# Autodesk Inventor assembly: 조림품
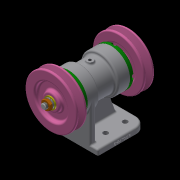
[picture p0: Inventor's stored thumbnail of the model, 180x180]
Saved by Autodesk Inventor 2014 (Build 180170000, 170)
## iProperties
Created: 2020-06
Part Number: 조림품
Document SubType Name: Assembly
Designer: kh
Author: kh
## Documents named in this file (12)
- C:\Users\kh\Desktop\700606V1034\조림품.iam
- C:\Users\kh\Desktop\700606V1034\본체.ipt
- C:\Users\kh\Desktop\700606V1034\베어링 6204.ipt
- C:\Users\kh\Desktop\700606V1034\축.ipt
- C:\Users\kh\Desktop\700606V1034\커버.ipt
- C:\Users\kh\Desktop\700606V1034\오일 실 20 32 5.ipt
- C:\Users\kh\Desktop\700606V1034\Ű 5x5x12.ipt
- C:\Users\kh\Desktop\700606V1034\V-벨트풀리.ipt
- C:\Users\kh\Desktop\700606V1034\평면 와셔 10x21.ipt
- C:\Users\kh\Desktop\700606V1034\스프링 와셔 10.ipt
- C:\Users\kh\Desktop\700606V1034\너트 M10.ipt
- C:\Users\kh\Desktop\700606V1034\볼트 M4.ipt
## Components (4 placed, 2 different names)
1. Ű 5x5x12:1 — Mate:17, Mate:18, Mate:23
2. Ű 5x5x12:2 — Mate:19, Mate:20, Mate:24
3. V-벨트풀리:1 — Mate:21, Mate:23, Flush:1, Mate:28
4. V-벨트풀리:2 — Mate:22, Mate:24, Flush:2, Mate:27
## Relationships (12: Mate 10, Flush 2)
- Mate:17: Ű 5x5x12:1
- Mate:18: Ű 5x5x12:1
- Mate:19: Ű 5x5x12:2
- Mate:20: Ű 5x5x12:2
- Mate:21: V-벨트풀리:1
- Mate:22: V-벨트풀리:2
- Mate:23: Ű 5x5x12:1 ↔ V-벨트풀리:1
- Mate:24: Ű 5x5x12:2 ↔ V-벨트풀리:2
- Flush:1: V-벨트풀리:1
- Flush:2: V-벨트풀리:2
- Mate:27: V-벨트풀리:2
- Mate:28: V-벨트풀리:1
